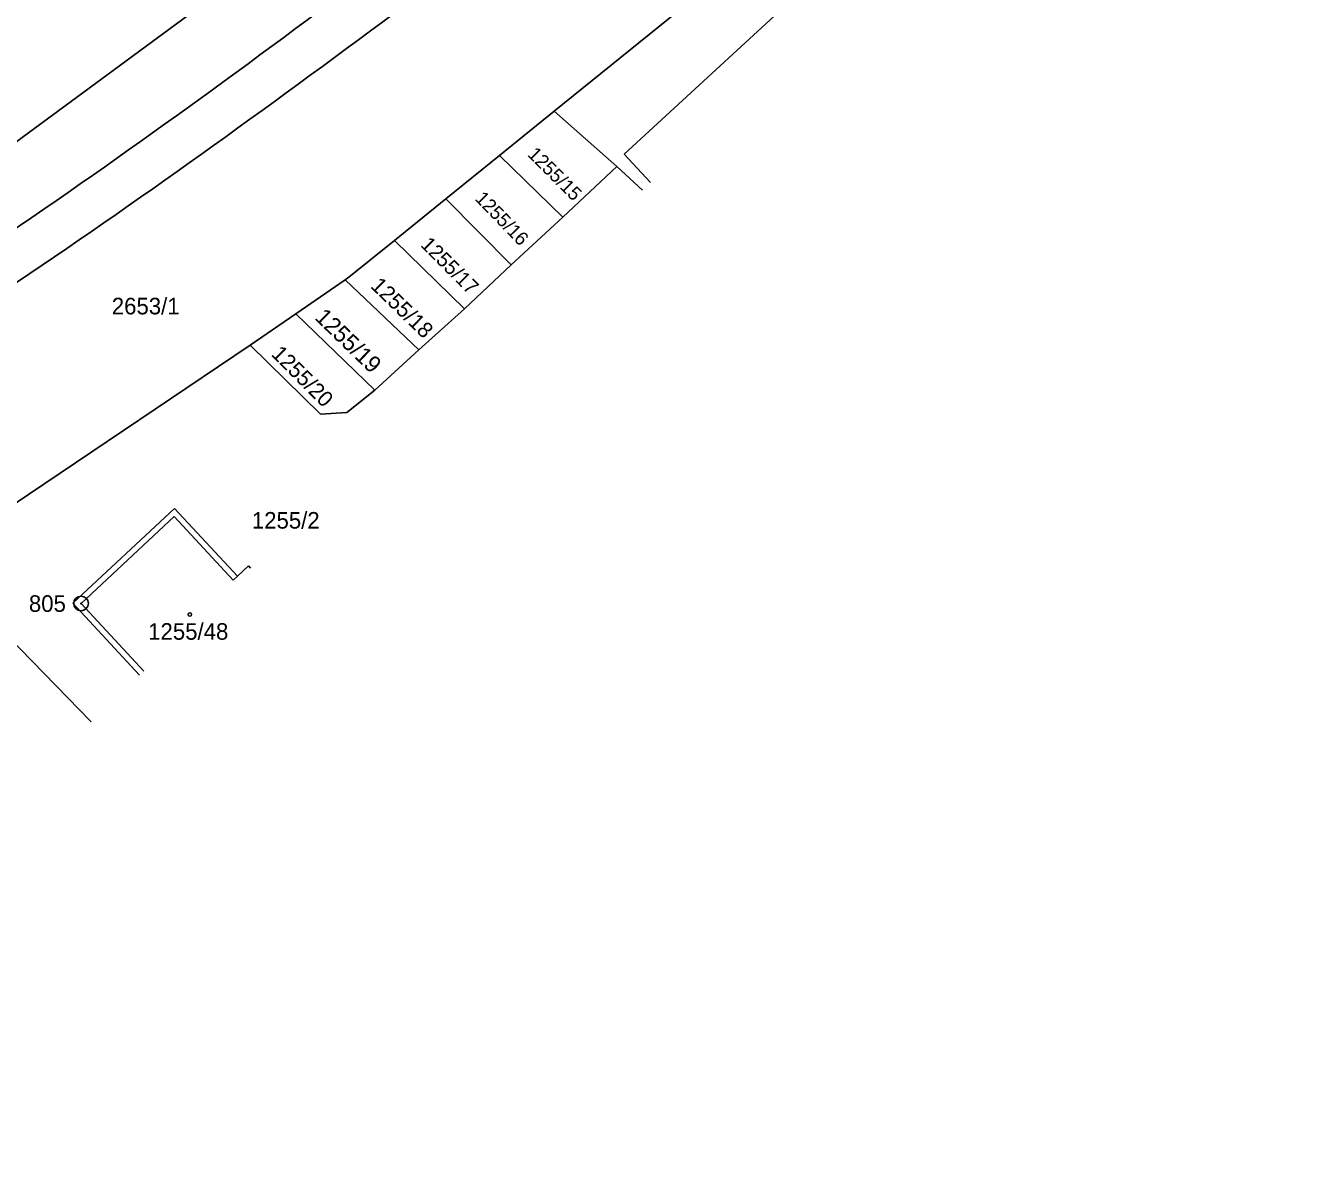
# Model space of a CAD drawing. Extents: x -825057 to -819383, y -1071633 to -1067888.
# Drawn here: x -820067.4 to -819936.8, y -1069550.5 to -1069432.8 of the extents above; entities that cross this region are included whole.
import ezdxf

# ---------------------------------------------------------------- set-up
doc = ezdxf.new("R2010")
doc.units = 0
for name, color, linetype in [('Vrstva 1', 7, 'Continuous'), ('Vrstva 10', 7, 'Continuous'), ('Vrstva 17', 7, 'Continuous'), ('Vrstva 18', 7, 'Continuous'), ('Vrstva 19', 7, 'Continuous'), ('Vrstva 24', 7, 'Continuous'), ('Vrstva 25', 7, 'Continuous'), ('Vrstva 4', 7, 'Continuous')]:
    doc.layers.add(name, color=color, linetype=linetype)

msp = doc.modelspace()

# ---------------------------------------------------------------- linework, layer by layer
at = {"layer": 'Vrstva 1'}
for p, q in [((-820006, -1069446.03), (-819947.67, -1069392.35)), ((-820013.16, -1069441.63), (-819961.4, -1069399.82)), ((-820018.78, -1069446.17), (-820013.16, -1069441.63)), ((-820006.72, -1069447.29), (-820013.16, -1069441.63)), ((-820024.28, -1069450.61), (-820018.78, -1069446.17)), ((-820018.78, -1069446.17), (-820012.28, -1069452.5)), ((-820003.28, -1069448.92), (-820006, -1069446.03)), ((-820012.28, -1069452.5), (-820006.72, -1069447.29)), ((-820004.11, -1069449.71), (-820006.72, -1069447.29)), ((-820029.55, -1069454.87), (-820024.28, -1069450.61)), ((-820024.28, -1069450.61), (-820017.56, -1069457.37)), ((-820017.56, -1069457.37), (-820012.28, -1069452.5)), ((-820034.23, -1069458.65), (-820029.55, -1069454.87)), ((-820029.55, -1069454.87), (-820022.36, -1069461.88)), ((-820022.36, -1069461.88), (-820017.56, -1069457.37)), ((-820039.64, -1069462.38), (-820034.6, -1069458.91)), ((-820034.6, -1069458.91), (-820034.23, -1069458.65)), ((-820034.6, -1069458.91), (-820027.03, -1069466.07)), ((-820027.03, -1069466.07), (-820022.36, -1069461.88)), ((-820044.32, -1069465.59), (-820039.64, -1069462.38)), ((-820039.64, -1069462.38), (-820031.54, -1069470.21)), ((-820070.35, -1069483.1), (-820044.32, -1069465.59)), ((-820037.13, -1069472.69), (-820044.32, -1069465.59)), ((-820031.54, -1069470.21), (-820027.03, -1069466.07)), ((-820034.43, -1069472.52), (-820031.54, -1069470.21)), ((-820037.13, -1069472.69), (-820034.43, -1069472.52)), ((-820052.09, -1069482.33), (-820062.53, -1069492.05)), ((-820045.65, -1069489.28), (-820052.09, -1069482.33)), ((-820076.89, -1069487.51), (-820060.65, -1069504.23)), ((-820044.51, -1069488.23), (-820045.65, -1069489.28)), ((-820044.3, -1069488.46), (-820044.51, -1069488.23)), ((-820062.53, -1069492.05), (-820055.67, -1069499.43))]:
    msp.add_line(p, q, dxfattribs=at)
at = {"layer": 'Vrstva 10'}
for points in [[(-819936.83, -1069349.47), (-819975.71, -1069383.16), (-819999.35, -1069402.16), (-820038.47, -1069432.26), (-820078.04, -1069460.09), (-820109.89, -1069479.65), (-820134.7, -1069493.27), (-820163.02, -1069506.83), (-820195.64, -1069520.53), (-820237.28, -1069534.88), (-820272.75, -1069545.33)], [(-820271.07, -1069550.51), (-820235.31, -1069539.9), (-820193.69, -1069525.37), (-820161.56, -1069511.74), (-820132.38, -1069497.54), (-820107.7, -1069483.92), (-820075.84, -1069464.22), (-820035.7, -1069436.13), (-819996.53, -1069406.13), (-819972.84, -1069386.82), (-819933.47, -1069352.83)]]:
    msp.add_spline(points, degree=3, dxfattribs=at)
at = {"layer": 'Vrstva 24'}
for radius in [0.75, 0.0327]:
    msp.add_circle((-820061.68, -1069492.08), radius, dxfattribs=at)
at = {"layer": 'Vrstva 25'}
msp.add_circle((-820050.52, -1069493.21), 0.175, dxfattribs=at)
at = {"layer": 'Vrstva 4'}
for p, q in [((-820076.53, -1069450.8), (-820004.18, -1069397.53)), ((-820061.68, -1069492.08), (-820052.12, -1069483.18)), ((-820052.12, -1069483.18), (-820046.09, -1069489.69)), ((-820045.65, -1069489.28), (-820046.09, -1069489.69)), ((-820055.24, -1069499.01), (-820061.68, -1069492.08))]:
    msp.add_line(p, q, dxfattribs=at)

# ---------------------------------------------------------------- texts
at = {"layer": 'Vrstva 17'}
msp.add_text('805', height=1.7, dxfattribs=at).set_placement((-820067.026, -1069492.94))
at = {"layer": 'Vrstva 18'}
for s, height, rotation, p in [('1255/15', 1.4, 315, (-820015.974, -1069446.136)), ('1255/16', 1.4, 314.1, (-820021.366, -1069450.659)), ('1255/17', 1.5, 315, (-820026.953, -1069455.407)), ('1255/18', 1.6, 315.9, (-820032.076, -1069459.637)), ('1255/19', 1.7, 315.9, (-820037.804, -1069462.88)), ('1255/20', 1.6, 315, (-820042.264, -1069466.616))]:
    msp.add_text(s, height=height, rotation=rotation, dxfattribs=at).set_placement(p)
for s, p in [('2653/1', (-820058.524, -1069462.45)), ('1255/2', (-820044.163, -1069484.41))]:
    msp.add_text(s, height=1.7, dxfattribs=at).set_placement(p)
at = {"layer": 'Vrstva 19'}
msp.add_text('1255/48', height=1.7, dxfattribs=at).set_placement((-820054.794, -1069495.8))

doc.saveas('drawing.dxf')
